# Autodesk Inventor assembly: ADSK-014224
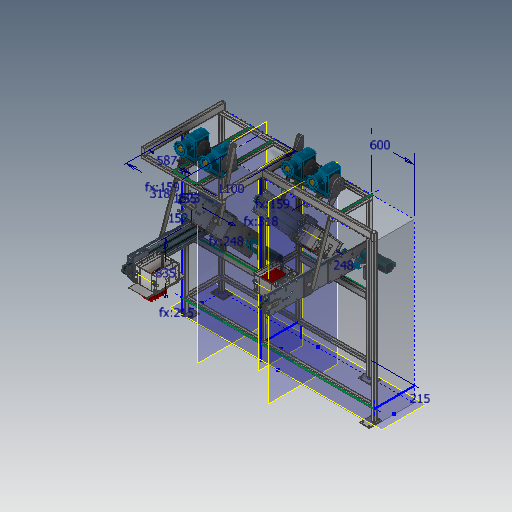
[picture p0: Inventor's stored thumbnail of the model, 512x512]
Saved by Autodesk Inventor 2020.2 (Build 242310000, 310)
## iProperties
Created: 2019-10
Part Number: ADSK-014224
Document SubType Name: Assembly
Designer: lutzd
Mass: 2.70318e+07 g
Surface Area: 516412 cm^2
Volume: 3.47339e+06 cm^3
Density: 7.78253 g/cm^3
VLDS_Profile: Default Assembly
VLDS_TimeStamp: 2016-07-29
VLDS_FailCnt: 0
VLDS_AcceptCnt: 0
Dimensions: 2023,6x2637,5x2753,9 mm
Mass: 27031,797 kg
DocNumber: ADSK-014224
Folder: 01 - Themengebiete\Simplification\01 - Packaging machine\
VDS_Category: 3D Komponenten
VDS_NumSchm: Autodesk
Title: SUB-119310-33N
Author: lutzd
Revision Number: -
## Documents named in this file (22)
- D:\07 - DEMODATEN\OTX 2019 - Dataset - UPDATE - Dez2019\Designs\07-Packing machine\ADSK-014224.iam
- D:\07 - DEMODATEN\OTX 2019 - Dataset - UPDATE - Dez2019\Designs\07-Packing machine\ADSK-014200.iam
- D:\07 - DEMODATEN\OTX 2019 - Dataset - UPDATE - Dez2019\Designs\07-Packing machine\Parts\ADSK-011619.ipt
- D:\07 - DEMODATEN\OTX 2019 - Dataset - UPDATE - Dez2019\Designs\07-Packing machine\102500-1A.iam
- D:\07 - DEMODATEN\OTX 2019 - Dataset - UPDATE - Dez2019\Content Center Files\de-DE\DIN 125-1  B\DIN 125-1 - B 13.ipt
- D:\07 - DEMODATEN\OTX 2019 - Dataset - UPDATE - Dez2019\Content Center Files\de-DE\ISO 4762(2)\ISO 4762 - M12 x 45ISO.ipt
- D:\07 - DEMODATEN\OTX 2019 - Dataset - UPDATE - Dez2019\Designs\07-Packing machine\500589.iam
- D:\07 - DEMODATEN\OTX 2019 - Dataset - UPDATE - Dez2019\Content Center Files\de-DE\ISO 2491 - A\ISO 2491 - A  10 x 6 x 45.ipt
- D:\07 - DEMODATEN\OTX 2019 - Dataset - UPDATE - Dez2019\Designs\07-Packing machine\Parts\ADSK-011689.ipt
- D:\07 - DEMODATEN\OTX 2019 - Dataset - UPDATE - Dez2019\Designs\07-Packing machine\Parts\ADSK-011603.ipt
- D:\07 - DEMODATEN\OTX 2019 - Dataset - UPDATE - Dez2019\Designs\07-Packing machine\Parts\ADSK-011688.ipt
- D:\07 - DEMODATEN\OTX 2019 - Dataset - UPDATE - Dez2019\Designs\07-Packing machine\103100.iam
- D:\07 - DEMODATEN\OTX 2019 - Dataset - UPDATE - Dez2019\Designs\07-Packing machine\103100-01.iam
- D:\07 - DEMODATEN\OTX 2019 - Dataset - UPDATE - Dez2019\Designs\07-Packing machine\Parts\ADSK-011244.ipt
- D:\07 - DEMODATEN\OTX 2019 - Dataset - UPDATE - Dez2019\Designs\07-Packing machine\103100-03.iam
- D:\07 - DEMODATEN\OTX 2019 - Dataset - UPDATE - Dez2019\Designs\07-Packing machine\110100-00.iam
- D:\07 - DEMODATEN\OTX 2019 - Dataset - UPDATE - Dez2019\Designs\07-Packing machine\103100-02.iam
- D:\07 - DEMODATEN\OTX 2019 - Dataset - UPDATE - Dez2019\Designs\07-Packing machine\102500-1B.iam
- D:\07 - DEMODATEN\OTX 2019 - Dataset - UPDATE - Dez2019\Designs\07-Packing machine\ADSK-014249.iam
- D:\07 - DEMODATEN\OTX 2019 - Dataset - UPDATE - Dez2019\Content Center Files\de-DE\DIN 9021\DIN 9021 - 8,4.ipt
- D:\07 - DEMODATEN\OTX 2019 - Dataset - UPDATE - Dez2019\Content Center Files\de-DE\ISO 4762(2)\ISO 4762 - M8 x 16ISO.ipt
- 102500-1B.iam
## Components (74 placed, 20 different names)
1. ADSK-014200:1 [sub-assembly] — Passend:1, Passend:2, Passend:3, Passend:4, Fluchtend:1, Passend:58, Passend:59, Passend:60, Passend:61, Passend:63, Passend:64, Passend:66, Passend:67, Passend:68, Passend:69, Passend:70, Passend:75, Passend:76, Passend:77, Passend:80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
2. ADSK-011619:1 — Passend:1, Passend:3, Passend:5, Passend:6, Passend:13, Passend:14, Passend:15, Passend:16, Fluchtend:117
3. ADSK-011619:2 — Passend:2, Passend:4, Fluchtend:1, Passend:7, Passend:8, Passend:9, Passend:10, Passend:11, Passend:12
4. 102500-1B:2 [sub-assembly] — Passend:5, Passend:15, Passend:16, Passend:49, Passend:50, Fluchtend:7, Passend:52, Fluchtend:10, Passend:54
5. 102500-1A:2 [sub-assembly] — Passend:6, Passend:13, Passend:14, Passend:18, Passend:20, Passend:22, Passend:24, Passend:47, Passend:48, Fluchtend:6, Passend:51, Fluchtend:9, Passend:55
6. 102500-1B:1 [sub-assembly] — Passend:7, Passend:11, Passend:12, Passend:45, Passend:46, Fluchtend:5, Passend:53, Fluchtend:8, Passend:56
7. 102500-1A:4 [sub-assembly] — Passend:8, Passend:9, Passend:10, Passend:41, Passend:42, Fluchtend:3, Passend:43, Passend:44, Fluchtend:4
8. 500589:1 [sub-assembly] — Passend:41, Passend:42, Fluchtend:3, Passend:137, Passend:144
9. 500589:2 [sub-assembly] — Passend:53, Fluchtend:8, Passend:56, Passend:150, Einfügen:5
10. 500589:3 [sub-assembly] — Passend:51, Fluchtend:9, Passend:55, Einfügen:10, Passend:153
11. 500589:4 [sub-assembly] — Passend:52, Fluchtend:10, Passend:54, Einfügen:8, Passend:154
12. ADSK-011689:1 — Passend:59, Passend:60, Passend:61, Passend:74, Passend:79
13. ADSK-011689:2 — Passend:58, Passend:63, Passend:64
14. ADSK-011689:3 — Passend:66, Passend:67, Passend:68
15. ADSK-011603:1 — Passend:69, Passend:70, Passend:71, Passend:72, Passend:73
16. ADSK-011689:4 — Passend:71, Passend:72, Passend:73, Passend:74, Passend:92
17. ADSK-011688:1 — Passend:78, Passend:80, Passend:85, Passend:86
18. ADSK-011688:2 — Passend:79, Passend:81, Passend:87, Passend:88
19. ADSK-011689:5 — Passend:75, Passend:76, Passend:77, Passend:78
20. ADSK-011689:6 — Passend:82, Passend:83, Passend:84
21. 103100:1 [sub-assembly] — Passend:85, Passend:89, Passend:102, Passend:103, Passend:104, Passend:111, Passend:119, Passend:120, Winkel:1, Passend:135, Passend:138
22. 103100:2 [sub-assembly] — Passend:86, Passend:90, Passend:99, Passend:100, Passend:101, Passend:112, Passend:123, Passend:124, Passend:159, Passend:160
23. 103100:3 [sub-assembly] — Passend:87, Passend:91, Passend:96, Passend:97, Passend:98, Passend:113, Passend:121, Passend:122, Passend:157, Passend:158
24. 103100:4 [sub-assembly] — Passend:88, Passend:92, Passend:93, Passend:94, Passend:95, Passend:114, Passend:125, Passend:126, Passend:155, Passend:156, STROKE
25. 103100-01:1 [sub-assembly] — Passend:99, Passend:100, Passend:101, Passend:106, Fluchtend:12, Fluchtend:114
26. 103100-01:2 [sub-assembly] — Passend:102, Passend:103, Passend:104, Passend:105, Passend:110, Fluchtend:113
27. 103100-01:3 [sub-assembly] — Passend:96, Passend:97, Passend:98, Passend:107, Passend:109, Fluchtend:115
28. 103100-01:4 [sub-assembly] — Passend:93, Passend:94, Passend:95, Passend:108, Fluchtend:11, Fluchtend:116
29. ADSK-011244:1 — Passend:108, Fluchtend:11, Passend:115
30. ADSK-011244:2 — Passend:107, Passend:109, Passend:116
31. ADSK-011244:3 — Passend:106, Fluchtend:12, Passend:117
32. ADSK-011244:4 — Passend:105, Passend:110, Passend:118
33. 103100-03:1 [sub-assembly] — Passend:112, Fluchtend:114, Passend:117
34. 103100-03:2 [sub-assembly] — Passend:113, Fluchtend:115, Passend:116
35. 103100-03:3 [sub-assembly] — Passend:114, Fluchtend:116, Passend:115
36. 103100-03:4 [sub-assembly] — Passend:111, Fluchtend:113, Passend:118
37. 110100-00:1 [sub-assembly] — Passend:119, Passend:120
38. 110100-00:2 [sub-assembly] — Passend:121, Passend:122
39. 103100-02:1 [sub-assembly] — Passend:125, Passend:126, STROKE
40. 103100-02:2 [sub-assembly] — Passend:123, Passend:124
41. ADSK-014249:1 [sub-assembly] — Passend:135, Passend:137, Passend:138
42. ADSK-014249:2 [sub-assembly] — Passend:150, Passend:159, Passend:160
43. ADSK-014249:3 [sub-assembly] — Passend:154, Passend:155, Passend:156
44. ADSK-014249:4 [sub-assembly] — Passend:153, Passend:157, Passend:158
45. DIN 9021 8,4:2
46. ISO 4762 M8 x 16:2
47. DIN 9021 8,4:1 — Passend:144, Passend:146
48. ISO 4762 M8 x 16:1 — Passend:146
49. DIN 9021 8,4:3 — Einfügen:5, Einfügen:6
50. ISO 4762 M8 x 16:3 — Einfügen:6
51. DIN 9021 8,4:6 — Einfügen:8
52. ISO 4762 M8 x 16:6
53. DIN 9021 8,4:7 — Einfügen:10
54. ISO 4762 M8 x 16:7
55. DIN 125-1 B B 13:1 — Passend:18
56. DIN 125-1 B B 13:2 — Passend:20
57. DIN 125-1 B B 13:3 — Passend:22
58. DIN 125-1 B B 13:4 — Passend:24
59. DIN 125-1 B B 13:5 — Passend:26, Passend:28, Passend:30, Passend:32, Passend:34, Passend:36, Passend:38, Passend:40
60. DIN 125-1 B B 13:6
61. DIN 125-1 B B 13:7
62. DIN 125-1 B B 13:8
63. ISO 4762 M12 x 45:1 — Passend:26
64. ISO 4762 M12 x 45:2 — Passend:28
65. ISO 4762 M12 x 45:3 — Passend:30
66. ISO 4762 M12 x 45:4 — Passend:32
67. ISO 4762 M12 x 45:5 — Passend:34
68. ISO 4762 M12 x 45:6 — Passend:36
69. ISO 4762 M12 x 45:7 — Passend:38
70. ISO 4762 M12 x 45:8 — Passend:40
71. ISO 2491 A A  10 x 6 x 45:1 — Passend:43, Passend:44, Fluchtend:4
72. ISO 2491 A A  10 x 6 x 45:2 — Passend:45, Passend:46, Fluchtend:5
73. ISO 2491 A A  10 x 6 x 45:3 — Passend:47, Passend:48, Fluchtend:6
74. ISO 2491 A A  10 x 6 x 45:4 — Passend:49, Passend:50, Fluchtend:7
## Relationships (147: Mate 125, Flush 17, Insert 4, Angle 1)
- STROKE [Flush]: 103100:4 ↔ 103100-02:1
- Passend:1 [Mate]: ADSK-014200:1 ↔ ADSK-011619:1
- Passend:2 [Mate]: ADSK-014200:1 ↔ ADSK-011619:2
- Passend:3 [Mate]: ADSK-014200:1 ↔ ADSK-011619:1
- Passend:4 [Mate]: ADSK-014200:1 ↔ ADSK-011619:2
- Fluchtend:1 [Flush]: ADSK-014200:1 ↔ ADSK-011619:2
- Passend:5 [Mate]: ADSK-011619:1 ↔ 102500-1B:2
- Passend:6 [Mate]: ADSK-011619:1 ↔ 102500-1A:2
- Passend:7 [Mate]: ADSK-011619:2 ↔ 102500-1B:1
- Passend:8 [Mate]: ADSK-011619:2 ↔ 102500-1A:4
- Passend:9 [Mate]: ADSK-011619:2 ↔ 102500-1A:4
- Passend:10 [Mate]: ADSK-011619:2 ↔ 102500-1A:4
- Passend:11 [Mate]: ADSK-011619:2 ↔ 102500-1B:1
- Passend:12 [Mate]: ADSK-011619:2 ↔ 102500-1B:1
- Passend:13 [Mate]: ADSK-011619:1 ↔ 102500-1A:2
- Passend:14 [Mate]: ADSK-011619:1 ↔ 102500-1A:2
- Passend:15 [Mate]: ADSK-011619:1 ↔ 102500-1B:2
- Passend:16 [Mate]: ADSK-011619:1 ↔ 102500-1B:2
- Passend:18 [Mate]: 102500-1A:2 ↔ DIN 125-1 B B 13:1
- Passend:20 [Mate]: 102500-1A:2 ↔ DIN 125-1 B B 13:2
- Passend:22 [Mate]: 102500-1A:2 ↔ DIN 125-1 B B 13:3
- Passend:24 [Mate]: 102500-1A:2 ↔ DIN 125-1 B B 13:4
- Passend:26 [Mate]: DIN 125-1 B B 13:5 ↔ ISO 4762 M12 x 45:1
- Passend:28 [Mate]: DIN 125-1 B B 13:5 ↔ ISO 4762 M12 x 45:2
- Passend:30 [Mate]: DIN 125-1 B B 13:5 ↔ ISO 4762 M12 x 45:3
- Passend:32 [Mate]: DIN 125-1 B B 13:5 ↔ ISO 4762 M12 x 45:4
- Passend:34 [Mate]: DIN 125-1 B B 13:5 ↔ ISO 4762 M12 x 45:5
- Passend:36 [Mate]: DIN 125-1 B B 13:5 ↔ ISO 4762 M12 x 45:6
- Passend:38 [Mate]: DIN 125-1 B B 13:5 ↔ ISO 4762 M12 x 45:7
- Passend:40 [Mate]: DIN 125-1 B B 13:5 ↔ ISO 4762 M12 x 45:8
- Passend:41 [Mate]: 102500-1A:4 ↔ 500589:1
- Passend:42 [Mate]: 102500-1A:4 ↔ 500589:1
- Fluchtend:3 [Flush]: 102500-1A:4 ↔ 500589:1
- Passend:43 [Mate]: 102500-1A:4 ↔ ISO 2491 A A  10 x 6 x 45:1
- Passend:44 [Mate]: 102500-1A:4 ↔ ISO 2491 A A  10 x 6 x 45:1
- Fluchtend:4 [Flush]: 102500-1A:4 ↔ ISO 2491 A A  10 x 6 x 45:1
- Passend:45 [Mate]: 102500-1B:1 ↔ ISO 2491 A A  10 x 6 x 45:2
- Passend:46 [Mate]: 102500-1B:1 ↔ ISO 2491 A A  10 x 6 x 45:2
- Fluchtend:5 [Flush]: 102500-1B:1 ↔ ISO 2491 A A  10 x 6 x 45:2
- Passend:47 [Mate]: 102500-1A:2 ↔ ISO 2491 A A  10 x 6 x 45:3
- Passend:48 [Mate]: 102500-1A:2 ↔ ISO 2491 A A  10 x 6 x 45:3
- Fluchtend:6 [Flush]: 102500-1A:2 ↔ ISO 2491 A A  10 x 6 x 45:3
- Passend:49 [Mate]: 102500-1B:2 ↔ ISO 2491 A A  10 x 6 x 45:4
- Passend:50 [Mate]: 102500-1B:2 ↔ ISO 2491 A A  10 x 6 x 45:4
- Fluchtend:7 [Flush]: 102500-1B:2 ↔ ISO 2491 A A  10 x 6 x 45:4
- Passend:51 [Mate]: 102500-1A:2 ↔ 500589:3
- Passend:52 [Mate]: 102500-1B:2 ↔ 500589:4
- Passend:53 [Mate]: 102500-1B:1 ↔ 500589:2
- Fluchtend:8 [Flush]: 102500-1B:1 ↔ 500589:2
- Fluchtend:9 [Flush]: 102500-1A:2 ↔ 500589:3
- Fluchtend:10 [Flush]: 102500-1B:2 ↔ 500589:4
- Passend:54 [Mate]: 102500-1B:2 ↔ 500589:4
- Passend:55 [Mate]: 102500-1A:2 ↔ 500589:3
- Passend:56 [Mate]: 102500-1B:1 ↔ 500589:2
- Passend:58 [Mate]: ADSK-014200:1 ↔ ADSK-011689:2
- Passend:59 [Mate]: ADSK-014200:1 ↔ ADSK-011689:1
- Passend:60 [Mate]: ADSK-014200:1 ↔ ADSK-011689:1
- Passend:61 [Mate]: ADSK-014200:1 ↔ ADSK-011689:1
- Passend:63 [Mate]: ADSK-014200:1 ↔ ADSK-011689:2
- Passend:64 [Mate]: ADSK-014200:1 ↔ ADSK-011689:2
- Passend:66 [Mate]: ADSK-014200:1 ↔ ADSK-011689:3
- Passend:67 [Mate]: ADSK-014200:1 ↔ ADSK-011689:3
- Passend:68 [Mate]: ADSK-014200:1 ↔ ADSK-011689:3
- Passend:69 [Mate]: ADSK-014200:1 ↔ ADSK-011603:1
- Passend:70 [Mate]: ADSK-014200:1 ↔ ADSK-011603:1
- Passend:71 [Mate]: ADSK-011603:1 ↔ ADSK-011689:4
- Passend:72 [Mate]: ADSK-011603:1 ↔ ADSK-011689:4
- Passend:73 [Mate]: ADSK-011603:1 ↔ ADSK-011689:4
- Passend:74 [Mate]: ADSK-011689:1 ↔ ADSK-011689:4
- Passend:75 [Mate]: ADSK-014200:1 ↔ ADSK-011689:5
- Passend:76 [Mate]: ADSK-014200:1 ↔ ADSK-011689:5
- Passend:77 [Mate]: ADSK-014200:1 ↔ ADSK-011689:5
- Passend:78 [Mate]: ADSK-011688:1 ↔ ADSK-011689:5
- Passend:79 [Mate]: ADSK-011689:1 ↔ ADSK-011688:2
- Passend:80 [Mate]: ADSK-014200:1 ↔ ADSK-011688:1
- Passend:81 [Mate]: ADSK-014200:1 ↔ ADSK-011688:2
- Passend:82 [Mate]: ADSK-014200:1 ↔ ADSK-011689:6
- Passend:83 [Mate]: ADSK-014200:1 ↔ ADSK-011689:6
- Passend:84 [Mate]: ADSK-014200:1 ↔ ADSK-011689:6
- Passend:85 [Mate]: ADSK-011688:1 ↔ 103100:1
- Passend:86 [Mate]: ADSK-011688:1 ↔ 103100:2
- Passend:87 [Mate]: ADSK-011688:2 ↔ 103100:3
- Passend:88 [Mate]: ADSK-011688:2 ↔ 103100:4
- Passend:89 [Mate]: ADSK-014200:1 ↔ 103100:1
- Passend:90 [Mate]: ADSK-014200:1 ↔ 103100:2
- Passend:91 [Mate]: ADSK-014200:1 ↔ 103100:3
- Passend:92 [Mate]: ADSK-011689:4 ↔ 103100:4
- Passend:93 [Mate]: 103100:4 ↔ 103100-01:4
- Passend:94 [Mate]: 103100:4 ↔ 103100-01:4
- Passend:95 [Mate]: 103100:4 ↔ 103100-01:4
- Passend:96 [Mate]: 103100:3 ↔ 103100-01:3
- Passend:97 [Mate]: 103100:3 ↔ 103100-01:3
- Passend:98 [Mate]: 103100:3 ↔ 103100-01:3
- Passend:99 [Mate]: 103100:2 ↔ 103100-01:1
- Passend:100 [Mate]: 103100:2 ↔ 103100-01:1
- Passend:101 [Mate]: 103100:2 ↔ 103100-01:1
- Passend:102 [Mate]: 103100:1 ↔ 103100-01:2
- Passend:103 [Mate]: 103100:1 ↔ 103100-01:2
- Passend:104 [Mate]: 103100:1 ↔ 103100-01:2
- Passend:105 [Mate]: 103100-01:2 ↔ ADSK-011244:4
- Passend:106 [Mate]: 103100-01:1 ↔ ADSK-011244:3
- Passend:107 [Mate]: 103100-01:3 ↔ ADSK-011244:2
- Passend:108 [Mate]: 103100-01:4 ↔ ADSK-011244:1
- Fluchtend:11 [Flush]: 103100-01:4 ↔ ADSK-011244:1
- Passend:109 [Mate]: 103100-01:3 ↔ ADSK-011244:2
- Fluchtend:12 [Flush]: 103100-01:1 ↔ ADSK-011244:3
- Passend:110 [Mate]: 103100-01:2 ↔ ADSK-011244:4
- Passend:111 [Mate]: 103100:1 ↔ 103100-03:4
- Fluchtend:113 [Flush]: 103100-01:2 ↔ 103100-03:4
- Passend:112 [Mate]: 103100:2 ↔ 103100-03:1
- Fluchtend:114 [Flush]: 103100-01:1 ↔ 103100-03:1
- Passend:113 [Mate]: 103100:3 ↔ 103100-03:2
- Fluchtend:115 [Flush]: 103100-01:3 ↔ 103100-03:2
- Passend:114 [Mate]: 103100:4 ↔ 103100-03:3
- Fluchtend:116 [Flush]: 103100-01:4 ↔ 103100-03:3
- Passend:115 [Mate]: ADSK-011244:1 ↔ 103100-03:3
- Passend:116 [Mate]: ADSK-011244:2 ↔ 103100-03:2
- Passend:117 [Mate]: ADSK-011244:3 ↔ 103100-03:1
- Passend:118 [Mate]: ADSK-011244:4 ↔ 103100-03:4
- Passend:119 [Mate]: 103100:1 ↔ 110100-00:1
- Passend:120 [Mate]: 103100:1 ↔ 110100-00:1
- Passend:121 [Mate]: 103100:3 ↔ 110100-00:2
- Passend:122 [Mate]: 103100:3 ↔ 110100-00:2
- Passend:123 [Mate]: 103100:2 ↔ 103100-02:2
- Passend:124 [Mate]: 103100:2 ↔ 103100-02:2
- Passend:125 [Mate]: 103100:4 ↔ 103100-02:1
- Passend:126 [Mate]: 103100:4 ↔ 103100-02:1
- Winkel:1 [Angle]: 103100:1
- Passend:135 [Mate]: 103100:1 ↔ ADSK-014249:1
- Passend:137 [Mate]: 500589:1 ↔ ADSK-014249:1
- Passend:138 [Mate]: 103100:1 ↔ ADSK-014249:1
- Passend:144 [Mate]: 500589:1 ↔ DIN 9021 8,4:1
- Passend:146 [Mate]: DIN 9021 8,4:1 ↔ ISO 4762 M8 x 16:1
- Passend:150 [Mate]: 500589:2 ↔ ADSK-014249:2
- Einfügen:5 [Insert]: 500589:2 ↔ DIN 9021 8,4:3
- Einfügen:6 [Insert]: DIN 9021 8,4:3 ↔ ISO 4762 M8 x 16:3
- Einfügen:8 [Insert]: 500589:4 ↔ DIN 9021 8,4:6
- Einfügen:10 [Insert]: 500589:3 ↔ DIN 9021 8,4:7
- Passend:153 [Mate]: 500589:3 ↔ ADSK-014249:4
- Passend:154 [Mate]: 500589:4 ↔ ADSK-014249:3
- Passend:155 [Mate]: 103100:4 ↔ ADSK-014249:3
- Passend:156 [Mate]: 103100:4 ↔ ADSK-014249:3
- Passend:157 [Mate]: 103100:3 ↔ ADSK-014249:4
- Passend:158 [Mate]: 103100:3 ↔ ADSK-014249:4
- Passend:159 [Mate]: 103100:2 ↔ ADSK-014249:2
- Passend:160 [Mate]: 103100:2 ↔ ADSK-014249:2
- Fluchtend:117 [Flush]: ADSK-014200:1 ↔ ADSK-011619:1
## Named parameters: d188_d187 = 0, d194_d193 = 0, d195_d188_d187 = 0, d197_d193 = 0, d198_d188_d187 = 0
